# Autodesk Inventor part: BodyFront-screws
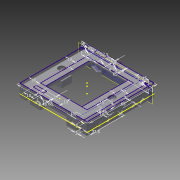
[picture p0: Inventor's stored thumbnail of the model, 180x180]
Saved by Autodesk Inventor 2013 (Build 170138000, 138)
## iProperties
Created: 2013-03
Part Number: BodyFront-screws
Material: Generic
Document SubType Name: Modeling
Designer: frankenteddy
Density: 1 g/cm^3
Author: frankenteddy
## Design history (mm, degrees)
sketch "Sketch1"
  geometry: L1 (-32.5, 32.5)-(32.5, 32.5); L2 (32.5, 32.5)-(32.5, -32.5); L3 (32.5, -32.5)-(-32.5, -32.5); L4 (-32.5, -32.5)-(-32.5, 32.5); L5 (-22.5, 32.5)-(-12.5, 32.5); L6 (-12.5, 32.5)-(-12.5, 29.5); L7 (-12.5, 29.5)-(-22.5, 29.5); L8 (-22.5, 29.5)-(-22.5, 32.5); L9 (32.5, 32.5)-(29.5, 32.5); L10 (29.5, 32.5)-(29.5, -32.5); L11 (29.5, -32.5)-(32.5, -32.5); L12 (32.5, -32.5)-(32.5, 32.5); L13 (-22.5, -26.5)-(-12.5, -26.5); L14 (-12.5, -26.5)-(-12.5, -29.5); L15 (-12.5, -29.5)-(-22.5, -29.5); L16 (-22.5, -29.5)-(-22.5, -26.5); L17 (-22.5, 22.5)-(22.5, 22.5); L18 (22.5, 22.5)-(22.5, -22.5); L19 (22.5, -22.5)-(-22.5, -22.5); L20 (-22.5, -22.5)-(-22.5, 22.5); L21 (24.5, 32.5)-(24.5, -32.5); L22 (32.5, 27.5)-(-32.5, 27.5); L23 (-17.5, 22.5)-(-17.5, -22.5); L24 (17.5, 22.5)-(17.5, -22.5); 7 further points
  constraints: 48 end point, 10 parallel, 10 point on line, 9 perpendicular, 5 horizontal, 4 coincident, 2 midpoint, 1 horizontal alignment, 1 vertical alignment
  dimensions: "d0" = 65 distance of L2.end L3.end; "d1" = 65 distance of L1.end L2.end; "d8" = 10 distance of L6.end L7.end; "d9" = 3 distance of L5.end L6.end; "d15" = 3 distance of L11.end L10.end; "d25" = 10 distance between parallel lines of L8 L4; "d26" = 10 distance of L14.end L15.end; "d27" = 3 distance of L13.end L14.end; "d28" = 3 distance between parallel lines of L15 L3; "d29" = 10 distance between parallel lines of L4 L16; "d38" = 10 distance between parallel lines of L17 L1; "d39" = 7 distance between parallel lines of L10 L18; "d40" = 10 distance between parallel lines of L4 L20; "d41" = 10 distance between parallel lines of L3 L19; "d45" = 5 distance between parallel lines of L10 L21; "d92" = 5 distance between parallel lines of L22 L1; "d131" = 5 distance between parallel lines of L20 L23; "d132" = 5 distance between parallel lines of L18 L24
extrude "Extrusion1" new body sketch "Sketch1" distance "d4" = 3; taper "d5" = 0 deg
extrude "Extrusion3" join sketch "Sketch1" distance "d10" = 13; taper "d11" = 0 deg
sketch "Sketch2"
  geometry: L1 (10, 13)-(20, 3); L2 (20, 13)-(10, 3); C1 r 2 at (15, 8); 2 further points
  constraints: 4 end point, 1 centre point, 1 coincident, 1 midpoint, 1 perpendicular
  dimensions: "d12" = 4 diameter of C1
extrude "Extrusion4" cut sketch "Sketch2" distance "d13" = 3; taper "d14" = 0 deg
extrude "Extrusion5" join sketch "Sketch1" distance "d16" = 9; taper "d17" = 0 deg
sketch "Sketch3"
  geometry: L1 (-32.5, -32.5)-(-29.5, -32.5) reference; L2 (-29.5, -32.5)-(-29.5, 32.5) reference; L3 (-29.5, 32.5)-(-32.5, 32.5) reference; L4 (-32.5, 32.5)-(-32.5, -32.5) reference; L5 (-29.5, 5)-(-19.5, 5); L6 (-19.5, 5)-(-19.5, -5); L7 (-19.5, -5)-(-29.5, -5); L8 (-29.5, -5)-(-29.5, 5); L9 (12.5, 32.5)-(-29.5, 32.5) reference; L10 (-29.5, 5)-(-19.5, -5); L11 (-19.5, 5)-(-29.5, -5); L12 (-29.5, -32.5)-(32.5, -32.5) reference; L13 (-24.5, 4.879)-(-20.275, 2.439); L14 (-20.275, 2.439)-(-20.275, -2.439); L15 (-20.275, -2.439)-(-24.5, -4.879); L16 (-24.5, -4.879)-(-28.725, -2.439); L17 (-28.725, -2.439)-(-28.725, 2.439); L18 (-28.725, 2.439)-(-24.5, 4.879); L19 (-29.5, 32.5)-(-26.5, 32.5); L20 (-26.5, 32.5)-(-26.5, 5); L21 (-26.5, 5)-(-29.5, 5); L22 (-29.5, 5)-(-29.5, 32.5); L23 (-29.5, -5)-(-26.5, -5); L24 (-26.5, -5)-(-26.5, -32.5); L25 (-26.5, -32.5)-(-29.5, -32.5); L26 (-29.5, -32.5)-(-29.5, -5); L27 (-29.5, 0)-(-19.5, 0); C1 r 2 at (-24.5, 0); 3 further points
  constraints: 42 end point, 6 parallel, 3 horizontal, 3 midpoint, 3 perpendicular, 3 point on line, 2 coincident, 1 centre point, 13 other
  dimensions: "d18" = 10 distance of L6.end L7.end; "d19" = 10 distance of L5.end L6.end; "d20" = 4 diameter of C1; "d68" = 8.45 distance between parallel lines of L14 L17; "d81" = 3 distance of L20.end L21.end; "d82" = 3 distance of L24.end L25.end; "d96" = 32.5 distance between parallel lines of L12 L27
extrude "Extrusion6" join sketch "Sketch3" distance "d21" = 3; taper "d22" = 0 deg
mirror "Mirror1"
mirror "Mirror2"
mirror "Mirror3"
extrude "Extrusion7" join sketch "Sketch1" distance "d30" = 13; taper "d31" = 0 deg
sketch "Sketch4"
  geometry: L1 (0, 10)-(10, 0); L2 (10, 10)-(0, 0); L3 (5, 9.879)-(9.225, 7.439); L4 (9.225, 7.439)-(9.225, 2.561); L5 (9.225, 2.561)-(5, 0.121); L6 (5, 0.121)-(0.775, 2.561); L7 (0.775, 2.561)-(0.775, 7.439); L8 (0.775, 7.439)-(5, 9.879); C1 r 1.75 at (5, 5); 3 further points
  constraints: 16 end point, 2 coincident, 1 centre point, 1 midpoint, 1 perpendicular, 13 other
  dimensions: "d32" = 3.5 diameter of C1; "d65" = 8.45 distance between parallel lines of L4 L7
extrude "Extrusion8" cut sketch "Sketch4" distance "d34" = 3; taper "d35" = 0 deg
mirror "Mirror4"
fillet "Fillet1" dims "d37" = 5
extrude "Extrusion9" cut sketch "Sketch1" distance "d42" = 3; taper "d43" = 0 deg
workplane "Work Plane1"
sketch "Sketch5"
  geometry: L1 (0, 0)-(-65, 0); L2 (-65, 0)-(-65, -3); L3 (-65, -3)-(0, -3); L4 (0, -3)-(0, 0); L5 (-32.5, 2.25)-(-32.5, -4.25); L6 (-20, 1.5)-(-20, -3.5); L7 (-45, 1.5)-(-45, -3.5); A1 r 2.5 centre (-45, -1) between (-45, -3.5) and (-45, 1.5); A2 r 3.25 centre (-32.5, -1) between (-32.5, 2.25) and (-32.5, -4.25); A3 r 2.5 centre (-20, -1) between (-20, 1.5) and (-20, -3.5); 2 further points
  constraints: 14 end point, 6 point on circle, 4 midpoint, 4 perpendicular, 3 centre point, 2 parallel, 1 horizontal, 1 other
  dimensions: "d108" = 65 distance of L3.end L2.end; "d109" = 3 distance of L2.end L1.end; "d110" = 32.5 distance between parallel lines of L5 L4; "d111" = 20 distance between parallel lines of L6 L4; "d112" = 20 distance between parallel lines of L2 L7; "d113" = 5 diameter of A1; "d114" = 6.5 diameter of A2; "d115" = 5 diameter of A3; "d116" = 1 distance from line of L1 A1.centre; "d117" = 1 distance from line of L1 A2.centre; "d118" = 1 distance from line of L1 A3.centre
sketch "Sketch6"
  geometry: L1 (-29.5, 32.5)-(-29.5, -32.5) reference; L2 (-22.5, 32.5)-(-29.5, 32.5); L3 (-29.5, 32.5)-(-29.5, 29.5); L4 (-29.5, 29.5)-(-22.5, 29.5); L5 (-22.5, 29.5)-(-22.5, 32.5); L6 (-12.5, 32.5)-(0, 32.5); L7 (0, 32.5)-(0, 29.5); L8 (0, 29.5)-(-12.5, 29.5); L9 (-12.5, 29.5)-(-12.5, 32.5); L10 (-29.5, -32.5)-(-22.5, -32.5) reference; L11 (-26.718, -32.5)-(-22.5, -32.5); L12 (-22.5, -32.5)-(-22.5, -26.5); L13 (-22.5, -26.5)-(-26.718, -26.5); L14 (-26.718, -26.5)-(-26.718, -32.5); L15 (-12.5, -32.5)-(0, -32.5); L16 (0, -32.5)-(0, -26.5); L17 (0, -26.5)-(-12.5, -26.5); L18 (-12.5, -26.5)-(-12.5, -32.5); 1 further point
  constraints: 32 end point, 8 parallel, 4 horizontal, 4 perpendicular, 2 point on line
  dimensions: "d85" = 3 distance between parallel lines of L8 L6; "d87" = 3 distance between parallel lines of L4 L2; "d88" = 6 distance of L12.end L11.end (derived); "d89" = 6 distance of L16.end L15.end
extrude "Extrusion10" join sketch "Sketch6" distance "d55" = 3; taper "d56" = 0 deg
mirror "Mirror7"
sketch "Sketch7"
  geometry: L1 (6, 27.5)-(0, 27.5) reference; L2 (0, 0)-(3, 0); L3 (3, 0)-(3, 27.5); L4 (3, 27.5)-(0, 27.5); L5 (0, 27.5)-(0, 0); L6 (0, -10)-(3, -10); L7 (3, -10)-(3, -37.5); L8 (3, -37.5)-(0, -37.5); L9 (0, -37.5)-(0, -10); 4 further points; 1 other entity
  constraints: 16 end point, 4 parallel, 2 horizontal, 2 perpendicular, 1 midpoint, 2 other
extrude "Extrusion11" join sketch "Sketch7" distance "d57" = 3; taper "d58" = 0 deg
mirror "Mirror9"
extrude "Extrusion12" cut sketch "Sketch4" distance "d66" = 3; taper "d67" = 0 deg
mirror "Mirror11"
extrude "Extrusion13" join sketch "Sketch3" distance "d69" = 3; taper "d70" = 0 deg
mirror "Mirror12"
workplane "Work Plane2"
extrude "Extrusion14" join sketch "Sketch3" distance "d83" = 6; taper "d84" = 0 deg
mirror "Mirror14"
extrude "Extrusion15" join sketch "Sketch6" distance "d90" = 3; taper "d91" = 0 deg
mirror "Mirror15"
mirror "Mirror16"
mirror "Mirror17"
workplane "Work Plane4"
sketch "Sketch9"
  geometry: L1 (0, 0)-(-65, 0) reference; L2 (-65, 0)-(-65, -3); L3 (-65, -3)-(0, -3); L4 (0, -3)-(0, 0) reference; L5 (-32.5, 0)-(-32.5, -3); L6 (-32.5, -3.5)-(-32.5, 1.5); L7 (-60, 1.5)-(-60, -3.5); L8 (-5, 1.5)-(-5, -3.5); A1 r 2.5 centre (-32.5, -1) between (-32.5, -3.5) and (-32.5, 1.5); A2 r 2.5 centre (-60, -1) between (-60, -3.5) and (-60, 1.5); A3 r 2.5 centre (-5, -1) between (-5, 1.5) and (-5, -3.5); 1 further point
  constraints: 16 end point, 6 point on circle, 5 midpoint, 4 perpendicular, 3 centre point, 2 horizontal, 2 parallel, 1 collinear, 1 point on line, 1 vertical
  dimensions: "d103" = 65 distance of L3.end L2.end; "d104" = 3 distance of L2.end L1.end; "d105" = 32.5 distance between parallel lines of L5 L4; "d106" = 5 diameter of A1; "d107" = 1 distance from line of A1.centre L1; "d119" = 5 distance between parallel lines of L2 L7; "d120" = 5 diameter of A2; "d121" = 1 distance from line of L1 A2.centre; "d122" = 5 distance between parallel lines of L8 L4; "d123" = 5 diameter of A3; "d124" = 1 distance from line of L1 A3.centre
extrude "Extrusion16" join sketch "Sketch1" distance "d133" = 3; taper "d134" = 0 deg
revolve "Revolution10" stored, may be unused: angle "d135" = 90 deg
mirror "Mirror20"
sketch "Sketch11"
  geometry: L1 (-7, 0)-(0, 0) reference; L2 (0, 65)-(0, 0) reference; L3 (-7, 65)-(0, 65); L4 (0, 65)-(0, 0); L5 (0, 0)-(-7, 0); L6 (-7, 0)-(-7, 65); L7 (-7, 32.5)-(0, 32.5); L8 (-3.5, 35.391)-(-0.996, 33.946); L9 (-0.996, 33.946)-(-0.996, 31.054); L10 (-0.996, 31.054)-(-3.5, 29.609); L11 (-3.5, 29.609)-(-6.004, 31.054); L12 (-6.004, 31.054)-(-6.004, 33.946); L13 (-6.004, 33.946)-(-3.5, 35.391); L14 (-7, 53)-(0, 53); L15 (-7, 12)-(0, 12); L16 (-7, 20.5)-(0, 20.5); L17 (-7, 44.5)-(0, 44.5); L18 (-3.5, 56.175)-(-0.75, 51.412); L19 (-0.75, 51.412)-(-6.25, 51.412); L20 (-6.25, 51.412)-(-3.5, 56.175); L21 (-3.5, 8.825)-(-6.25, 13.588); L22 (-6.25, 13.588)-(-0.75, 13.588); L23 (-0.75, 13.588)-(-3.5, 8.825); C1 r 2 at (-3.5, 44.5); C2 r 2 at (-3.5, 20.5); 4 further points
  constraints: 42 end point, 8 point on line, 7 midpoint, 4 parallel, 3 perpendicular, 2 centre point, 1 horizontal, 27 other
  dimensions: "d145" = 7 distance of L1.end L5.end (derived); "d146" = 65 distance of L3.end L1.end (derived); "d147" = 12 distance between parallel lines of L14 L3; "d148" = 12 distance between parallel lines of L15 L1; "d149" = 12 distance between parallel lines of L16 L7; "d150" = 12 distance between parallel lines of L17 L7; "d151" = 5.5 distance of L18.end L19.end; "d152" = 5.5 distance of L21.end L22.end; "d153" = 4 diameter of C1; "d154" = 4 diameter of C2
extrude "Extrusion19" cut sketch "Sketch11" distance "d155" = 1.5; taper "d156" = 0 deg
mirror "Mirror21"
sketch "Sketch13"
  geometry: L1 (-16.161, -22.601)-(16.752, -22.601); L2 (16.752, -22.601)-(16.752, -26.339); L3 (16.752, -26.339)-(-16.161, -26.339); L4 (-16.161, -26.339)-(-16.161, -22.601); 1 further point
  constraints: 2 other
emboss "Emboss3" sketch "Sketch13" dims "d159" = 2, "d160" = 0
body "Solid1"
